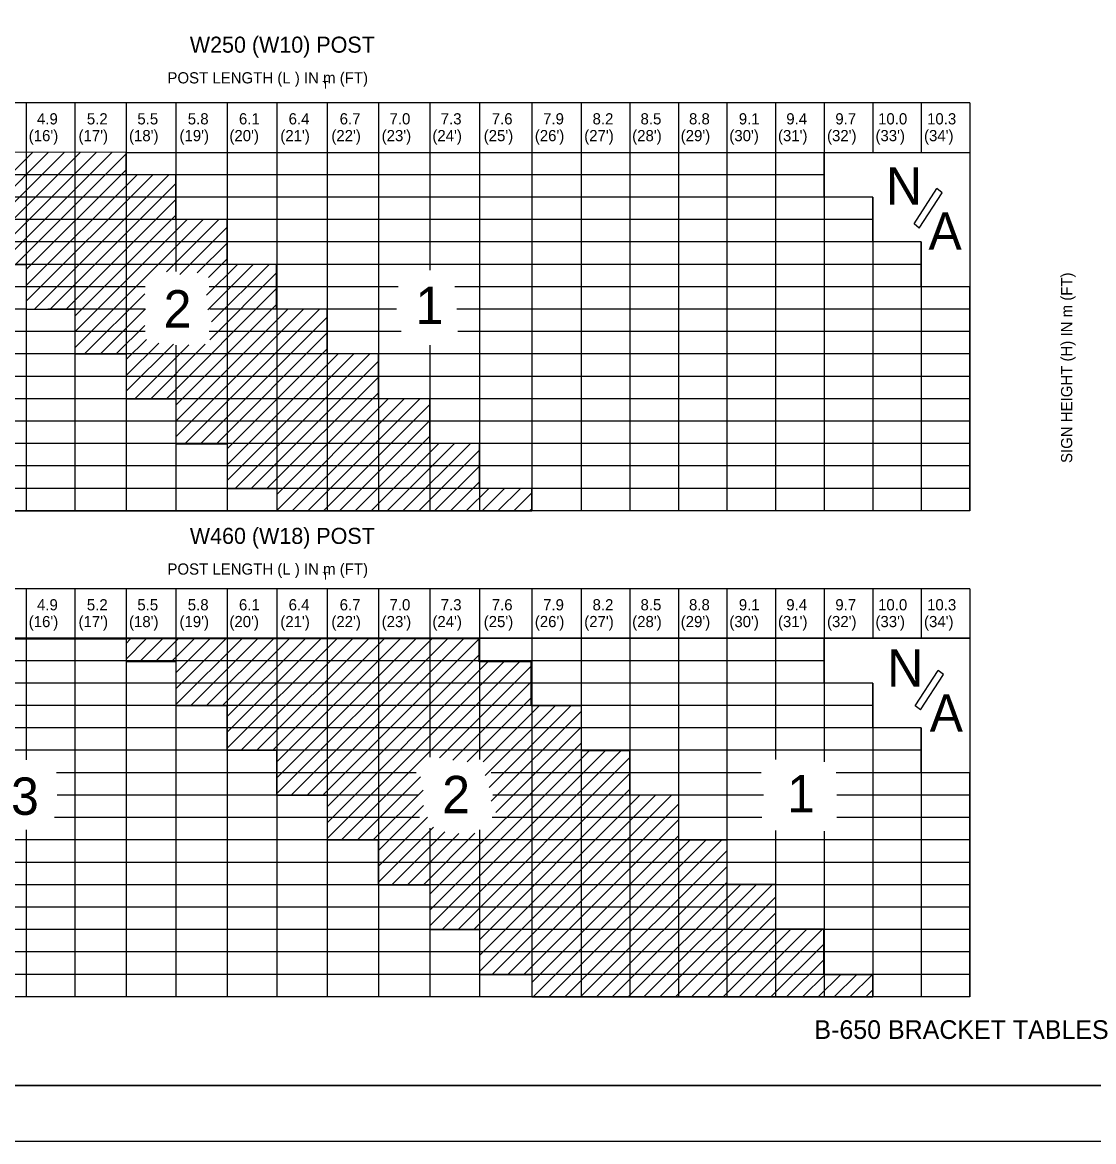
# Model space of a CAD drawing. Extents: x 637580 to 641008, y 294594 to 295782.
# Drawn here: x 639427.3 to 639714, y 294593.6 to 294893.4 of the extents above; entities that cross this region are included whole.
import ezdxf

# ---------------------------------------------------------------- set-up
doc = ezdxf.new("R2010")
doc.units = 0
for name, color, linetype in [('1', 7, 'Continuous'), ('2', 7, 'Continuous'), ('PLT-BNDY', 7, 'Continuous')]:
    doc.layers.add(name, color=color, linetype=linetype)

msp = doc.modelspace()

# ---------------------------------------------------------------- linework, layer by layer
at = {"layer": '1'}
for p, q in [((640088.31, 294608.63), (639302.31, 294608.63)), ((639302.31, 294608.63), (639888.31, 294608.63))]:
    msp.add_line(p, q, dxfattribs=at)
at = {"layer": '2'}
for p, q in [((639680.91, 294871.85), (639360.51, 294871.85)), ((639428.3, 294871.85), (639428.3, 294810.59)), ((639441.3, 294871.85), (639441.3, 294762.59)), ((639455.06, 294871.85), (639455.06, 294762.59)), ((639468.32, 294871.85), (639468.32, 294826.64)), ((639482.07, 294871.85), (639482.07, 294762.59)), ((639495.33, 294871.85), (639495.33, 294762.59)), ((639508.84, 294871.85), (639508.84, 294762.59)), ((639522.6, 294871.85), (639522.6, 294762.59)), ((639536.35, 294871.85), (639536.35, 294827.06)), ((639549.61, 294871.85), (639549.61, 294762.59)), ((639563.62, 294871.85), (639563.62, 294762.59)), ((639576.87, 294871.85), (639576.87, 294762.59)), ((639589.88, 294871.85), (639589.88, 294762.59)), ((639602.88, 294871.85), (639602.88, 294762.59)), ((639615.89, 294871.85), (639615.89, 294762.59)), ((639628.89, 294871.85), (639628.89, 294762.59)), ((639641.9, 294871.85), (639641.9, 294762.59)), ((639654.9, 294871.85), (639654.9, 294858.59)), ((639667.91, 294871.85), (639667.91, 294858.59)), ((639680.91, 294871.85), (639680.91, 294762.59)), ((639455.06, 294858.59), (639393.34, 294858.64)), ((639412, 294840.6), (639430.04, 294858.64)), ((639414.28, 294838.64), (639434.28, 294858.64)), ((639414.28, 294834.4), (639438.48, 294858.59)), ((639414.28, 294830.15), (639442.72, 294858.59)), ((639416.99, 294828.62), (639446.96, 294858.59)), ((639421.23, 294828.62), (639451.2, 294858.59)), ((639425.48, 294828.62), (639455.06, 294858.21)), ((639455.06, 294852.59), (639455.06, 294858.59)), ((639455.06, 294858.59), (639641.9, 294858.59)), ((639641.9, 294858.59), (639680.91, 294858.59)), ((639641.9, 294846.59), (639641.9, 294858.59)), ((639680.91, 294858.59), (639680.91, 294822.59)), ((639428.28, 294827.19), (639455.1, 294854)), ((639641.9, 294852.59), (639326.28, 294852.59)), ((639428.28, 294822.95), (639457.94, 294852.6)), ((639428.28, 294818.7), (639462.18, 294852.6)), ((639430.45, 294816.63), (639466.42, 294852.6)), ((639434.69, 294816.63), (639468.25, 294850.18)), ((639468.32, 294852.59), (639455.06, 294852.59)), ((639468.32, 294840.59), (639468.32, 294852.59)), ((639654.9, 294846.59), (639326.28, 294846.59)), ((639438.93, 294816.63), (639468.32, 294846.01)), ((639654.9, 294846.59), (639641.9, 294846.59)), ((639654.9, 294834.59), (639654.9, 294846.59)), ((639654.9, 294846.59), (639654.9, 294762.59)), ((639441.31, 294814.76), (639468.32, 294841.77)), ((639654.9, 294840.59), (639326.28, 294840.59)), ((639441.31, 294810.52), (639471.39, 294840.59)), ((639441.31, 294806.28), (639475.63, 294840.59)), ((639465.85, 294826.57), (639479.87, 294840.59)), ((639482.08, 294840.59), (639468.32, 294840.59)), ((639469.38, 294825.86), (639482.05, 294838.53)), ((639482.08, 294828.59), (639482.08, 294840.59)), ((639667.91, 294834.59), (639326.28, 294834.59)), ((639474.06, 294826.29), (639482.05, 294834.29)), ((639667.91, 294834.59), (639654.9, 294834.59)), ((639667.91, 294822.59), (639667.91, 294834.59)), ((639667.91, 294834.59), (639667.91, 294762.59)), ((639477.05, 294825.04), (639482.05, 294830.04)), ((639667.91, 294828.59), (639326.28, 294828.59)), ((639414.29, 294828.59), (639428.3, 294828.59)), ((639428.3, 294828.59), (639428.3, 294816.59)), ((639476.55, 294820.3), (639484.83, 294828.59)), ((639476.92, 294816.43), (639489.08, 294828.59)), ((639477.4, 294808.42), (639495.31, 294826.33)), ((639477.9, 294813.16), (639493.32, 294828.59)), ((639495.31, 294828.59), (639482.08, 294828.59)), ((639495.31, 294816.58), (639495.31, 294828.59)), ((639428.3, 294822.59), (639326.28, 294822.59)), ((639460.15, 294822.59), (639428.3, 294822.59)), ((639443.9, 294804.62), (639460, 294820.72)), ((639465.84, 294792.62), (639495.31, 294822.09)), ((639527.82, 294822.59), (639477.23, 294822.59)), ((639680.91, 294822.59), (639543.01, 294822.59)), ((639680.91, 294822.59), (639667.91, 294822.59)), ((639680.91, 294762.59), (639680.91, 294822.59)), ((639468.33, 294790.87), (639495.31, 294817.85)), ((639428.3, 294816.59), (639326.28, 294816.59)), ((639428.3, 294816.59), (639441.3, 294816.59)), ((639460.15, 294816.59), (639434.07, 294816.59)), ((639441.3, 294816.59), (639441.3, 294804.59)), ((639448.14, 294804.62), (639460.23, 294816.71)), ((639468.33, 294786.63), (639498.29, 294816.58)), ((639468.33, 294782.38), (639502.53, 294816.58)), ((639470.74, 294780.55), (639506.78, 294816.58)), ((639474.98, 294780.55), (639508.89, 294814.46)), ((639527.39, 294816.59), (639477.44, 294816.59)), ((639508.84, 294816.58), (639495.31, 294816.58)), ((639508.84, 294804.59), (639508.84, 294816.58)), ((639680.91, 294816.59), (639543.53, 294816.59)), ((639452.39, 294804.62), (639460, 294812.24)), ((639428.3, 294810.59), (639326.28, 294810.59)), ((639428.3, 294810.59), (639428.3, 294762.59)), ((639460.15, 294810.59), (639428.3, 294810.59)), ((639455.08, 294803.07), (639460.44, 294808.43)), ((639528.67, 294810.59), (639477.23, 294810.59)), ((639479.22, 294780.55), (639508.89, 294810.22)), ((639680.91, 294810.59), (639543.83, 294810.59)), ((639455.08, 294798.83), (639463.77, 294807.52)), ((639455.08, 294794.59), (639467.71, 294807.21)), ((639457.35, 294792.62), (639471.78, 294807.05)), ((639461.6, 294792.62), (639476.19, 294807.21)), ((639468.32, 294806.99), (639468.32, 294762.59)), ((639482.07, 294779.15), (639508.89, 294805.97)), ((639536.35, 294806.99), (639536.35, 294762.59)), ((639680.91, 294804.59), (639394.62, 294804.59)), ((639441.3, 294804.59), (639455.06, 294804.59)), ((639455.06, 294804.59), (639455.06, 294792.62)), ((639482.07, 294774.91), (639511.79, 294804.63)), ((639482.07, 294770.66), (639516.03, 294804.63)), ((639484.24, 294768.59), (639520.28, 294804.63)), ((639488.48, 294768.59), (639522.64, 294802.75)), ((639522.6, 294804.59), (639508.84, 294804.59)), ((639522.6, 294792.59), (639522.6, 294804.59)), ((639680.91, 294798.59), (639397.99, 294798.59)), ((639492.72, 294768.59), (639522.64, 294798.51)), ((639495.33, 294766.95), (639522.64, 294794.26)), ((639680.91, 294792.59), (639398.13, 294792.59)), ((639455.06, 294792.62), (639468.33, 294792.62)), ((639468.33, 294792.62), (639468.33, 294780.55)), ((639495.33, 294762.71), (639525.2, 294792.58)), ((639499.45, 294762.59), (639529.44, 294792.58)), ((639503.74, 294762.64), (639533.69, 294792.58)), ((639507.98, 294762.64), (639536.37, 294791.03)), ((639536.35, 294792.59), (639522.6, 294792.59)), ((639536.35, 294780.59), (639536.35, 294792.59)), ((639680.91, 294786.59), (639393.98, 294786.59)), ((639512.23, 294762.64), (639536.37, 294786.79)), ((639516.47, 294762.64), (639536.37, 294782.54)), ((639680.91, 294780.59), (639326.28, 294780.59)), ((639468.33, 294780.55), (639482.07, 294780.55)), ((639482.07, 294780.55), (639482.07, 294768.59)), ((639520.71, 294762.64), (639538.71, 294780.63)), ((639524.96, 294762.64), (639542.95, 294780.63)), ((639529.2, 294762.64), (639547.19, 294780.63)), ((639533.44, 294762.64), (639549.61, 294778.81)), ((639549.61, 294780.59), (639536.35, 294780.59)), ((639549.61, 294768.59), (639549.61, 294780.59)), ((639680.91, 294774.59), (639326.28, 294774.59)), ((639537.68, 294762.64), (639549.61, 294774.57)), ((639541.93, 294762.64), (639549.61, 294770.33)), ((639680.91, 294768.59), (639326.28, 294768.59)), ((639482.07, 294768.59), (639495.33, 294768.59)), ((639495.33, 294768.59), (639495.33, 294762.59)), ((639546.17, 294762.64), (639552.12, 294768.59)), ((639563.62, 294768.59), (639549.61, 294768.59)), ((639550.41, 294762.64), (639556.36, 294768.59)), ((639554.65, 294762.64), (639560.61, 294768.59)), ((639558.9, 294762.64), (639563.63, 294767.37)), ((639563.62, 294762.59), (639563.62, 294768.59)), ((639563.14, 294762.64), (639563.63, 294763.13)), ((639680.91, 294762.59), (639326.28, 294762.59)), ((639360.51, 294762.59), (639495.33, 294762.59)), ((639495.33, 294762.59), (639563.62, 294762.59)), ((639680.91, 294762.59), (639563.62, 294762.59)), ((639680.91, 294741.69), (639360.51, 294741.69)), ((639428.3, 294741.69), (639428.3, 294695.92)), ((639441.3, 294741.69), (639441.3, 294632.43)), ((639455.06, 294741.69), (639455.06, 294632.43)), ((639468.32, 294741.69), (639468.32, 294632.43)), ((639482.07, 294741.69), (639482.07, 294632.43)), ((639495.33, 294741.69), (639495.33, 294632.43)), ((639508.84, 294741.69), (639508.84, 294632.43)), ((639522.6, 294741.69), (639522.6, 294632.43)), ((639536.35, 294741.69), (639536.35, 294696.6)), ((639549.61, 294741.69), (639549.61, 294695.97)), ((639563.62, 294741.69), (639563.62, 294632.43)), ((639576.87, 294741.69), (639576.87, 294632.43)), ((639589.88, 294741.69), (639589.88, 294632.43)), ((639602.88, 294741.69), (639602.88, 294632.43)), ((639615.89, 294741.69), (639615.89, 294632.43)), ((639628.89, 294741.69), (639628.89, 294695.97)), ((639641.9, 294741.69), (639641.9, 294695.34)), ((639654.9, 294741.69), (639654.9, 294728.43)), ((639667.91, 294741.69), (639667.91, 294728.43)), ((639680.91, 294741.69), (639680.91, 294632.43)), ((639680.91, 294728.43), (639326.28, 294728.43)), ((639360.51, 294728.43), (639455.01, 294728.25)), ((639455.01, 294728.25), (639455.01, 294722.25)), ((639460.51, 294728.25), (639455.01, 294728.25)), ((639455.01, 294727.07), (639456.19, 294728.25)), ((639455.01, 294722.83), (639460.43, 294728.25)), ((639458.68, 294722.25), (639464.67, 294728.24)), ((639549.56, 294728.19), (639460.51, 294728.25)), ((639462.92, 294722.25), (639468.91, 294728.24)), ((639467.16, 294722.25), (639473.15, 294728.24)), ((639468.32, 294719.16), (639477.39, 294728.24)), ((639468.32, 294714.92), (639481.63, 294728.23)), ((639468.32, 294710.68), (639485.87, 294728.23)), ((639472.32, 294710.44), (639490.12, 294728.23)), ((639476.57, 294710.44), (639494.36, 294728.23)), ((639480.81, 294710.44), (639498.6, 294728.22)), ((639482.03, 294707.41), (639502.84, 294728.22)), ((639482.03, 294703.17), (639507.08, 294728.22)), ((639482.03, 294698.93), (639511.32, 294728.22)), ((639485.78, 294698.44), (639515.56, 294728.21)), ((639490.02, 294698.44), (639519.8, 294728.21)), ((639494.26, 294698.44), (639524.04, 294728.21)), ((639495.31, 294695.24), (639528.28, 294728.21)), ((639495.31, 294691), (639532.52, 294728.2)), ((639495.31, 294686.75), (639536.76, 294728.2)), ((639499.21, 294686.41), (639541, 294728.2)), ((639503.45, 294686.41), (639545.24, 294728.2)), ((639507.7, 294686.41), (639549.48, 294728.19)), ((639549.56, 294722.13), (639549.56, 294728.19)), ((639549.61, 294728.43), (639641.9, 294728.43)), ((639641.9, 294728.43), (639680.91, 294728.43)), ((639641.9, 294716.43), (639641.9, 294728.43)), ((639680.91, 294728.43), (639680.91, 294692.43)), ((639508.81, 294683.29), (639549.56, 294724.03)), ((639641.9, 294722.43), (639326.28, 294722.43)), ((639455.01, 294722.25), (639468.32, 294722.25)), ((639468.32, 294722.25), (639468.32, 294710.44)), ((639508.81, 294679.04), (639551.9, 294722.13)), ((639508.81, 294674.8), (639556.14, 294722.13)), ((639512.71, 294674.45), (639560.38, 294722.13)), ((639538.91, 294696.41), (639563.49, 294720.99)), ((639563.49, 294722.13), (639549.56, 294722.13)), ((639563.49, 294710.39), (639563.49, 294722.13)), ((639654.9, 294716.43), (639326.28, 294716.43)), ((639542.52, 294695.79), (639563.49, 294716.75)), ((639654.9, 294716.43), (639641.9, 294716.43)), ((639654.9, 294704.43), (639654.9, 294716.43)), ((639654.9, 294716.43), (639654.9, 294632.43)), ((639546.33, 294695.35), (639563.49, 294712.5)), ((639654.9, 294710.43), (639326.28, 294710.43)), ((639468.32, 294710.44), (639482.03, 294710.44)), ((639482.03, 294710.44), (639482.03, 294698.44)), ((639550.61, 294695.39), (639565.62, 294710.39)), ((639551.18, 294691.72), (639569.86, 294710.39)), ((639552.21, 294688.5), (639574.1, 294710.39)), ((639576.9, 294710.39), (639563.49, 294710.39)), ((639576.9, 294698.33), (639576.9, 294710.39)), ((639552.73, 294684.78), (639576.9, 294708.94)), ((639667.91, 294704.43), (639326.28, 294704.43)), ((639553.97, 294681.78), (639576.9, 294704.7)), ((639667.91, 294704.43), (639654.9, 294704.43)), ((639667.91, 294692.43), (639667.91, 294704.43)), ((639667.91, 294704.43), (639667.91, 294632.43)), ((639536.32, 294659.88), (639576.9, 294700.46)), ((639667.91, 294698.43), (639326.28, 294698.43)), ((639482.03, 294698.44), (639495.31, 294698.44)), ((639495.31, 294698.44), (639495.31, 294686.41)), ((639536.32, 294655.64), (639579.01, 294698.33)), ((639536.32, 294651.4), (639583.25, 294698.33)), ((639539.64, 294650.48), (639587.49, 294698.33)), ((639589.9, 294698.33), (639576.9, 294698.33)), ((639589.9, 294686.4), (639589.9, 294698.33)), ((639543.88, 294650.48), (639589.9, 294696.49)), ((639532.71, 294692.43), (639436.35, 294692.43)), ((639516.95, 294674.45), (639533.83, 294691.34)), ((639548.13, 294650.48), (639589.9, 294692.25)), ((639625.02, 294692.43), (639552.77, 294692.43)), ((639680.91, 294692.43), (639645.09, 294692.43)), ((639680.91, 294692.43), (639667.91, 294692.43)), ((639680.91, 294632.43), (639680.91, 294692.43)), ((639549.6, 294647.7), (639589.9, 294688)), ((639533.13, 294686.43), (639436.54, 294686.43)), ((639495.31, 294686.41), (639508.81, 294686.41)), ((639508.81, 294686.41), (639508.81, 294674.45)), ((639521.19, 294674.45), (639534.51, 294687.77)), ((639549.6, 294643.46), (639592.54, 294686.4)), ((639549.6, 294639.22), (639596.78, 294686.4)), ((639553.02, 294638.4), (639601.02, 294686.4)), ((639625.65, 294686.43), (639553.2, 294686.43)), ((639602.96, 294686.4), (639589.9, 294686.4)), ((639602.96, 294674.38), (639602.96, 294686.4)), ((639680.91, 294686.43), (639645.3, 294686.43)), ((639522.53, 294671.54), (639534.66, 294683.68)), ((639557.26, 294638.4), (639602.96, 294684.1)), ((639533.55, 294680.43), (639435.89, 294680.43)), ((639522.53, 294667.3), (639535.71, 294680.49)), ((639625.23, 294680.43), (639552.99, 294680.43)), ((639561.51, 294638.4), (639602.96, 294679.86)), ((639680.91, 294680.43), (639645.3, 294680.43)), ((639428.3, 294677.11), (639428.3, 294632.43)), ((639522.53, 294663.06), (639537.32, 294677.86)), ((639526.15, 294662.44), (639540.33, 294676.62)), ((639530.4, 294662.44), (639544.13, 294676.18)), ((639534.64, 294662.44), (639548.41, 294676.22)), ((639536.35, 294677.58), (639536.35, 294632.43)), ((639549.61, 294677.16), (639549.61, 294632.43)), ((639628.89, 294676.95), (639628.89, 294632.43)), ((639641.9, 294676.74), (639641.9, 294632.43)), ((639680.91, 294674.43), (639387.78, 294674.43)), ((639508.81, 294674.45), (639522.53, 294674.45)), ((639522.53, 294674.45), (639522.53, 294662.44)), ((639563.6, 294636.25), (639602.96, 294675.61)), ((639563.96, 294632.37), (639605.98, 294674.38)), ((639568.2, 294632.37), (639610.22, 294674.38)), ((639572.44, 294632.37), (639614.46, 294674.38)), ((639615.91, 294674.38), (639602.96, 294674.38)), ((639615.91, 294662.51), (639615.91, 294674.38)), ((639576.69, 294632.37), (639615.91, 294671.59)), ((639680.91, 294668.43), (639387.78, 294668.43)), ((639580.93, 294632.37), (639615.91, 294667.35)), ((639680.91, 294662.43), (639387.78, 294662.43)), ((639522.53, 294662.44), (639536.32, 294662.44)), ((639536.32, 294662.44), (639536.32, 294650.48)), ((639585.17, 294632.37), (639615.91, 294663.1)), ((639589.41, 294632.37), (639619.56, 294662.51)), ((639593.66, 294632.37), (639623.8, 294662.51)), ((639597.9, 294632.37), (639628.04, 294662.51)), ((639628.93, 294662.51), (639615.91, 294662.51)), ((639628.93, 294650.49), (639628.93, 294662.51)), ((639602.14, 294632.37), (639628.93, 294659.15)), ((639680.91, 294656.43), (639387.78, 294656.43)), ((639606.39, 294632.37), (639628.93, 294654.91)), ((639680.91, 294650.43), (639326.28, 294650.43)), ((639536.32, 294650.48), (639549.6, 294650.48)), ((639549.6, 294650.48), (639549.6, 294638.4)), ((639610.63, 294632.37), (639628.93, 294650.67)), ((639614.87, 294632.37), (639633, 294650.49)), ((639619.11, 294632.37), (639637.24, 294650.49)), ((639623.36, 294632.37), (639641.48, 294650.49)), ((639641.78, 294650.49), (639628.93, 294650.49)), ((639641.78, 294638.33), (639641.78, 294650.49)), ((639627.6, 294632.37), (639641.78, 294646.54)), ((639680.91, 294644.43), (639326.28, 294644.43)), ((639631.84, 294632.37), (639641.78, 294642.3)), ((639680.91, 294638.43), (639326.28, 294638.43)), ((639549.6, 294638.4), (639563.6, 294638.4)), ((639563.6, 294638.4), (639563.6, 294632.37)), ((639636.08, 294632.37), (639642.05, 294638.33)), ((639640.33, 294632.37), (639646.29, 294638.33)), ((639654.94, 294638.33), (639641.78, 294638.33)), ((639644.57, 294632.37), (639650.54, 294638.33)), ((639648.81, 294632.37), (639654.78, 294638.33)), ((639654.94, 294632.37), (639654.94, 294638.33)), ((639653.05, 294632.37), (639654.94, 294634.25)), ((639680.91, 294632.43), (639326.28, 294632.43)), ((639563.62, 294632.43), (639360.51, 294632.43)), ((639563.6, 294632.37), (639654.94, 294632.37)), ((639680.91, 294632.43), (639654.9, 294632.43))]:
    msp.add_line(p, q, dxfattribs=at)
for points in [[(639665.96, 294839.44), (639672.1, 294848.89)], [(639667.38, 294838.33), (639673.52, 294847.78)], [(639673.52, 294847.78), (639672.1, 294848.89)], [(639667.38, 294838.33), (639665.96, 294839.44)], [(639666.28, 294710.36), (639672.42, 294719.8)], [(639667.7, 294709.25), (639673.84, 294718.7)], [(639673.84, 294718.7), (639672.42, 294719.8)], [(639667.7, 294709.25), (639666.28, 294710.36)]]:
    msp.add_lwpolyline(points, dxfattribs=at)
at = {"layer": 'PLT-BNDY'}
msp.add_lwpolyline([(639262.31, 295187.63), (640103.31, 295187.63), (640103.31, 294593.63), (639262.31, 294593.63)], close=True, dxfattribs=at)

# ---------------------------------------------------------------- texts
at = {"layer": '2'}
for s, height, p in [('W250 (W10) POST', 4.3, (639472.08, 294885.29)), ('POST LENGTH (L ) IN m (FT)', 3, (639466.08, 294877.06)), ('T', 2, (639507.61, 294875.68)), ('4.9', 3, (639431.16, 294866.08)), ('5.2', 3, (639444.51, 294866.08)), ('5.5', 3, (639458.03, 294866.08)), ('5.8', 3, (639471.53, 294866.08)), ('6.1', 3, (639485.23, 294866.08)), ('6.4', 3, (639498.53, 294866.08)), ('6.7', 3, (639512.2, 294866.08)), ('7.0', 3, (639525.54, 294866.08)), ('7.3', 3, (639539.25, 294866.08)), ('7.6', 3, (639552.91, 294866.08)), ('7.9', 3, (639566.66, 294866.08)), ('8.2', 3, (639579.9, 294866.08)), ('8.5', 3, (639592.74, 294866.08)), ('8.8', 3, (639605.72, 294866.08)), ('9.1', 3, (639619.06, 294866.08)), ('9.4', 3, (639631.77, 294866.08)), ('9.7', 3, (639644.9, 294866.08)), ('10.0', 3, (639656.34, 294866.08)), ('10.3', 3, (639669.46, 294866.08)), ("(16')", 3, (639428.95, 294861.58)), ("(17')", 3, (639442.28, 294861.58)), ("(18')", 3, (639455.8, 294861.58)), ("(19')", 3, (639469.31, 294861.58)), ("(20')", 3, (639482.68, 294861.58)), ("(21')", 3, (639496.3, 294861.58)), ("(22')", 3, (639509.97, 294861.58)), ("(23')", 3, (639523.44, 294861.58)), ("(24')", 3, (639537.02, 294861.58)), ("(25')", 3, (639550.76, 294861.58)), ("(26')", 3, (639564.44, 294861.58)), ("(27')", 3, (639577.67, 294861.58)), ("(28')", 3, (639590.51, 294861.58)), ("(29')", 3, (639603.5, 294861.58)), ("(30')", 3, (639616.52, 294861.58)), ("(31')", 3, (639629.54, 294861.58)), ("(32')", 3, (639642.67, 294861.58)), ("(33')", 3, (639655.64, 294861.58)), ("(34')", 3, (639668.64, 294861.58)), ('N', 10, (639658.46, 294844.6)), ('A', 10, (639669.83, 294832.49)), ('2', 10, (639465.07, 294811.68)), ('1', 10, (639532.52, 294812.6)), ('W460 (W18) POST', 4.3, (639472.08, 294753.72)), ('POST LENGTH (L ) IN m (FT)', 3, (639466.08, 294745.49)), ('T', 2, (639507.61, 294744.11)), ('4.9', 3, (639431.16, 294735.92)), ('5.2', 3, (639444.51, 294735.92)), ('5.8', 3, (639471.53, 294735.92)), ('6.1', 3, (639485.23, 294735.92)), ('6.4', 3, (639498.53, 294735.92)), ('6.7', 3, (639512.2, 294735.92)), ('7.0', 3, (639525.54, 294735.92)), ('7.3', 3, (639539.25, 294735.92)), ('7.6', 3, (639552.91, 294735.92)), ('7.9', 3, (639566.66, 294735.92)), ('8.2', 3, (639579.9, 294735.92)), ('8.5', 3, (639592.74, 294735.92)), ('8.8', 3, (639605.72, 294735.92)), ('9.1', 3, (639619.06, 294735.92)), ('9.4', 3, (639631.77, 294735.92)), ('9.7', 3, (639644.9, 294735.92)), ('10.0', 3, (639656.34, 294735.92)), ('10.3', 3, (639669.46, 294735.92)), ('5.5', 3, (639458.03, 294735.92)), ("(16')", 3, (639428.95, 294731.42)), ("(17')", 3, (639442.28, 294731.42)), ("(18')", 3, (639455.8, 294731.42)), ("(19')", 3, (639469.31, 294731.42)), ("(20')", 3, (639482.68, 294731.42)), ("(21')", 3, (639496.3, 294731.42)), ("(22')", 3, (639509.97, 294731.42)), ("(23')", 3, (639523.44, 294731.42)), ("(24')", 3, (639537.02, 294731.42)), ("(25')", 3, (639550.76, 294731.42)), ("(26')", 3, (639564.44, 294731.42)), ("(27')", 3, (639577.67, 294731.42)), ("(28')", 3, (639590.51, 294731.42)), ("(29')", 3, (639603.5, 294731.42)), ("(30')", 3, (639616.52, 294731.42)), ("(31')", 3, (639629.54, 294731.42)), ("(32')", 3, (639642.67, 294731.42)), ("(33')", 3, (639655.64, 294731.42)), ("(34')", 3, (639668.64, 294731.42)), ('N', 10, (639658.78, 294715.52)), ('A', 10, (639670.15, 294703.41)), ('3', 10, (639424.21, 294681.16)), ('2', 10, (639539.65, 294681.59)), ('1', 10, (639631.97, 294681.82)), ('B-650 BRACKET TABLES', 5, (639639.3, 294621.13))]:
    msp.add_text(s, height=height, dxfattribs=at).set_placement(p)
msp.add_text('SIGN HEIGHT (H) IN m (FT)', height=3, rotation=90, dxfattribs=at).set_placement((639708.32, 294775.39))

doc.saveas('drawing.dxf')
